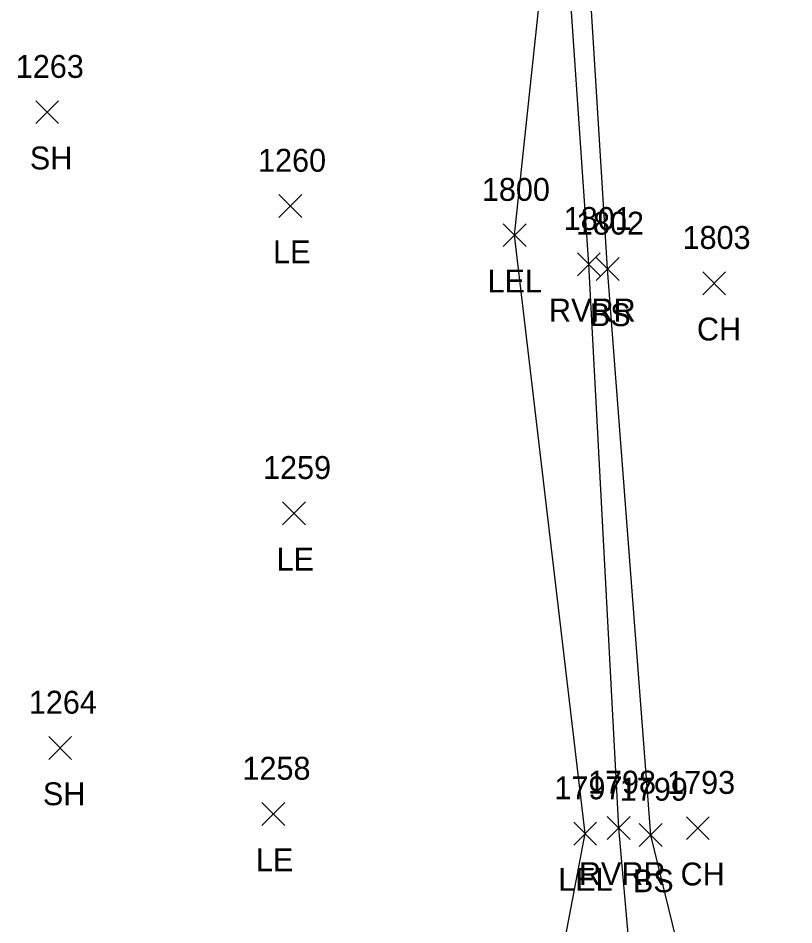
# Model space of a CAD drawing. Extents: x 1545627 to 1546562, y 571176 to 576667.
# Drawn here: x 1546025.3 to 1546093.1, y 571977 to 572056.2 of the extents above; entities that cross this region are included whole.
import ezdxf

# ---------------------------------------------------------------- set-up
doc = ezdxf.new("R2010")
doc.units = 0
for name, color, linetype in [('L_A', 7, 'Continuous'), ('L_I', 7, 'Continuous'), ('L_TIC', 7, 'Continuous'), ('LARO', 7, 'Continuous'), ('LAWE', 7, 'Continuous'), ('LELB', 7, 'Continuous')]:
    doc.layers.add(name, color=color, linetype=linetype)

msp = doc.modelspace()

# ---------------------------------------------------------------- linework, layer by layer
at = {"layer": 'L_TIC'}
for points in [[(1546026.811, 572047.027), (1546028.811, 572049.027)], [(1546028.811, 572047.027), (1546026.811, 572049.027)], [(1546048.077, 572038.826), (1546050.077, 572040.826)], [(1546050.077, 572038.826), (1546048.077, 572040.826)], [(1546067.68, 572036.281), (1546069.68, 572038.281)], [(1546069.68, 572036.281), (1546067.68, 572038.281)], [(1546074.176, 572033.738), (1546076.176, 572035.738)], [(1546076.176, 572033.738), (1546074.176, 572035.738)], [(1546075.818, 572033.333), (1546077.818, 572035.333)], [(1546077.818, 572033.333), (1546075.818, 572035.333)], [(1546085.135, 572032.08), (1546087.135, 572034.08)], [(1546087.135, 572032.08), (1546085.135, 572034.08)], [(1546048.386, 572011.979), (1546050.386, 572013.979)], [(1546050.386, 572011.979), (1546048.386, 572013.979)], [(1546027.951, 571991.473), (1546029.951, 571993.473)], [(1546029.951, 571991.473), (1546027.951, 571993.473)], [(1546046.58, 571985.702), (1546048.58, 571987.702)], [(1546048.58, 571985.702), (1546046.58, 571987.702)], [(1546076.788, 571984.488), (1546078.788, 571986.488)], [(1546078.788, 571984.488), (1546076.788, 571986.488)], [(1546083.707, 571984.464), (1546085.707, 571986.464)], [(1546085.707, 571984.464), (1546083.707, 571986.464)], [(1546073.853, 571983.992), (1546075.853, 571985.992)], [(1546075.853, 571983.992), (1546073.853, 571985.992)], [(1546079.581, 571983.869), (1546081.581, 571985.869)], [(1546081.581, 571983.869), (1546079.581, 571985.869)]]:
    msp.add_lwpolyline(points, dxfattribs=at)
at = {"layer": 'LARO'}
msp.add_lwpolyline([(1546090.217, 571893.115), (1546091.346, 571950.483), (1546086.619, 571960.2), (1546079.438, 571966.947), (1546072.29, 571971.504), (1546074.853, 571984.992), (1546068.68, 572037.281), (1546072.514, 572073.367), (1546063.142, 572085.778)], dxfattribs=at)
at = {"layer": 'LAWE'}
msp.add_lwpolyline([(1546079.438, 571966.947), (1546077.788, 571985.488), (1546075.176, 572034.738), (1546072.514, 572073.367), (1546072.957, 572091.545), (1546079.326, 572109.636), (1546089.965, 572133.875), (1546098.205, 572146.168), (1546103.269, 572146.803), (1546106.386, 572149.622), (1546130.143, 572181.263), (1546136.759, 572192.153), (1546140.729, 572200.768), (1546161.621, 572243.317), (1546187.565, 572282.786), (1546232.645, 572334.154), (1546255.297, 572360.235), (1546268.959, 572391.116)], dxfattribs=at)
at = {"layer": 'LELB'}
msp.add_lwpolyline([(1546086.619, 571960.2), (1546080.581, 571984.869), (1546076.818, 572034.333), (1546074.317, 572074.312)], dxfattribs=at)

# ---------------------------------------------------------------- texts
at = {"layer": 'L_A'}
for s, p in [('SH', (1546026.299, 572043.027)), ('LE', (1546047.565, 572034.826)), ('LEL', (1546066.317, 572032.281)), ('RVRR', (1546071.687, 572029.738)), ('BS', (1546075.259, 572029.333)), ('CH', (1546084.624, 572028.08)), ('LE', (1546047.874, 572007.979)), ('SH', (1546027.439, 571987.473)), ('LE', (1546046.068, 571981.702)), ('RVRR', (1546074.3, 571980.488)), ('CH', (1546083.195, 571980.464)), ('LEL', (1546072.491, 571979.992)), ('BS', (1546079.022, 571979.869))]:
    msp.add_text(s, height=2, dxfattribs=at).set_placement(p)
at = {"layer": 'L_I'}
for s, p in [('1263', (1546025.07, 572051.027)), ('1260', (1546046.25, 572042.826)), ('1800', (1546065.821, 572040.281)), ('1801', (1546072.971, 572037.738)), ('1802', (1546074.046, 572037.333)), ('1803', (1546083.364, 572036.08)), ('1259', (1546046.685, 572015.979)), ('1264', (1546026.211, 571995.473)), ('1258', (1546044.887, 571989.702)), ('1798', (1546075.095, 571988.488)), ('1793', (1546082.014, 571988.464)), ('1797', (1546072.16, 571987.992)), ('1799', (1546077.88, 571987.869))]:
    msp.add_text(s, height=2, dxfattribs=at).set_placement(p)

doc.saveas('drawing.dxf')
